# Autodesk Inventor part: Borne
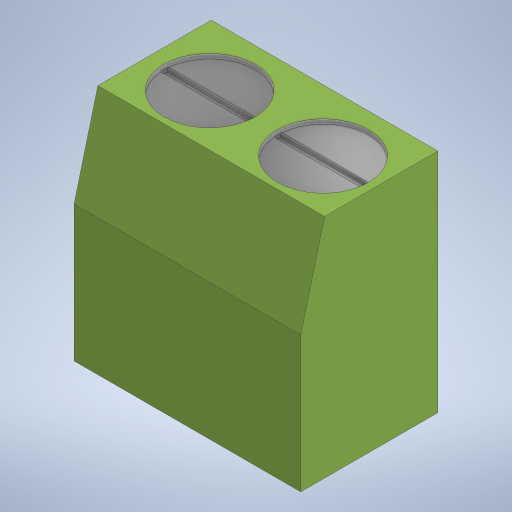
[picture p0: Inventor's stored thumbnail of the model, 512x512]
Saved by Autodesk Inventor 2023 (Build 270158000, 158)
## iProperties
Created: 2025-02
Part Number: Borne
Material: Générique
Document SubType Name: Modeling
Designer: bruno
Density: 1 g/cm^3
Appearance: Par défaut
Author: bruno
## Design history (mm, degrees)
sketch "Esquisse1"
  geometry: L1 (0, 0)-(6, 0); L2 (0, -6.049)-(0, 0); L3 (6, 0)-(10, -1.049); L4 (10, -1.049)-(10, -6.049); L5 (10, -6.049)-(0, -6.049)
  constraints: 10 end point, 1 horizontal, 1 perpendicular, 1 vertical
  dimensions: "d3" = 5 distance of L3.end L4.end; "d4" = 10 distance between parallel lines of L2 L4
extrude "Extrusion1" new body sketch "Esquisse1" distance "d5" = 10; taper "d6" = 0 deg
sketch "Esquisse4"
  geometry: L1 (0.75, 6.951)-(4.569, 6.951) reference; L2 (0.75, 6.951)-(0.75, 5.951) reference; L3 (4.569, 6.951)-(4.569, 5.951) reference; L4 (5.75, 6.951)-(9.569, 6.951) reference; L5 (5.75, 6.951)-(5.75, 5.951) reference; L6 (9.569, 6.951)-(9.569, 5.951) reference; L7 (10.75, 6.951)-(14.569, 6.951) reference; L8 (10.75, 6.951)-(10.75, 4.951) reference; L9 (10.75, 4.951)-(14.569, 4.951) reference; L10 (14.569, 6.951)-(14.569, 4.951) reference; L11 (2.66, 4.951)-(2.66, -0.409); L12 (9.569, 5.951)-(5.75, 5.951) reference; L13 (4.569, 5.951)-(0.75, 5.951) reference; C1 r 2.012 at (2.66, 2.271); 1 further point
  constraints: 2 end point, 1 centre point, 1 midpoint, 1 vertical
extrude "Extrusion4" cut sketch "Esquisse4" distance "d14" = 0.2; taper "d15" = 0 deg
sketch "Esquisse5"
  geometry: L1 (-2.052, -0.162)-(2.168, -0.162); L2 (2.168, -0.162)-(2.168, 0.18); L3 (2.168, 0.18)-(-2.052, 0.18); L4 (-2.052, 0.18)-(-2.052, -0.162); 1 further point
  constraints: 8 end point, 2 parallel, 1 horizontal, 1 perpendicular
extrude "Extrusion5" cut sketch "Esquisse5" distance "d16" = 0.2; taper "d17" = 0 deg
pattern_linear "Réseau rectangulaire2" dims "d20" = 5
node "Solide1"
